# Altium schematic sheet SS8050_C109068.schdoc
size 127 x 101 mm
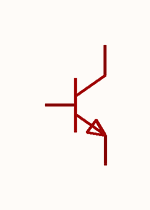
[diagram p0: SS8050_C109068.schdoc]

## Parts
Q?  ss8050(range:200-350)  [SOT-323-3_L2.2-W1.3-P1.30-LS2.1-BR]  (value not drawn)

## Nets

Not connected (* = marked no-connect by the designer): Q? 1 2 3

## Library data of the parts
Q? = ss8050(range:200-350): 晶体管类型:NPN;集电极电流(Ic):1.5A;集射极击穿电压(Vceo):25V;耗散功率(Pd):250mW;直流电流增益(hFE):200;; Manufacturer: CJ(江苏长电/长晶); Symbol: SS8050_C109068; AddInBom: yes; ModelId: 59529c0d6fc749f28f2d0659e12986b4; ModelName: SOT-323-3_L2.0-W1.3-H1.0-LS2.1-P1.30; ModelTransform: 78.74,82.677,0,90,0,0,-0.001,-0.001,0; type: NPN; Current - Collector(Ic): 1.5A; Collector - Emitter Voltage VCEO: 25V; Pd - Power Dissipation: 250mW; DC Current Gain: 200; Transition frequency(fT): 100MHz; Current - Collector Cutoff: 100nA; Vce Saturation(VCE(sat)): 500mV; Emitter-Base Voltage(Vebo): 5V; Number: 1个NPN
